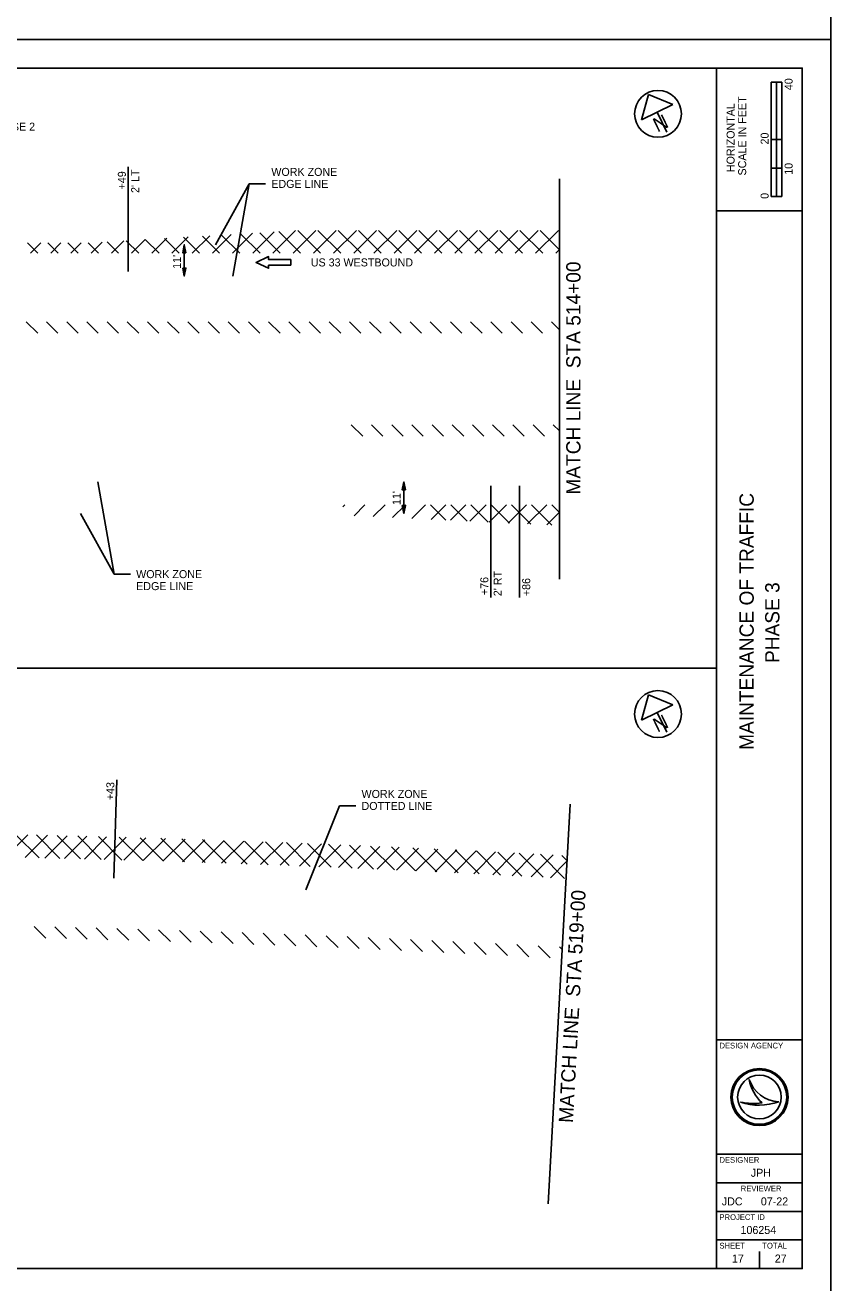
# Model space of a CAD drawing. Extents: x 0 to 5770, y -1320 to 440.
# Drawn here: x 3758.5 to 4040.6, y -435 to 5 of the extents above; entities that cross this region are included whole.
import ezdxf

# ---------------------------------------------------------------- set-up
doc = ezdxf.new("R2010")
doc.units = 0
for name, color, linetype in [('_CIVIL_CONSTRUCTION', 7, 'Continuous'), ('GE_P_Alignment', 7, 'Continuous'), ('GE_P_Alignment_100_Bearings', 7, 'Continuous'), ('GE_P_Alignment_100_Cardinal_Points', 7, 'Continuous'), ('GE_P_Alignment_100_Curve_Data', 7, 'Continuous'), ('GE_P_Alignment_100_Distances', 7, 'Continuous'), ('GE_P_Alignment_100_Stations', 7, 'Continuous'), ('HY_X_Water_Edge', 7, 'Continuous')]:
    doc.layers.add(name, color=color, linetype=linetype)

msp = doc.modelspace()

# ---------------------------------------------------------------- linework, layer by layer
at = {"layer": '_CIVIL_CONSTRUCTION'}
for points in [[(3360.58, 0), (4040.58, 0), (4040.58, 440), (3360.58, 440)], [(3360.58, -440), (4040.58, -440), (4040.58, 0), (3360.58, 0)]]:
    msp.add_lwpolyline(points, close=True, dxfattribs=at)
at = {"layer": 'GE_P_Alignment'}
for p, q in [((4000.58, -430), (4000.58, -10)), ((4000.58, -60), (4030.58, -60)), ((4000.58, -350), (4030.58, -350)), ((4000.58, -390), (4030.58, -390)), ((4000.58, -400), (4030.58, -400)), ((4000.58, -410), (4030.58, -410)), ((4000.58, -420), (4030.58, -420))]:
    msp.add_line(p, q, dxfattribs=at)
msp.add_lwpolyline([(3390.58, -10), (4030.58, -10), (4030.58, -430), (3390.58, -430)], close=True, dxfattribs=at)
at = {"layer": 'GE_P_Alignment_100_Bearings'}
for p, q in [((4019.71, -55), (4019.71, -15)), ((4023.46, -15), (4019.71, -15)), ((4019.71, -35), (4019.71, -15)), ((4019.71, -15), (4021.58, -15)), ((4021.58, -15), (4021.6, -15)), ((4021.6, -15), (4021.6, -35)), ((4023.46, -15), (4023.46, -55)), ((4021.6, -35), (4019.71, -35)), ((4023.45, -35), (4021.58, -35)), ((4021.58, -35), (4021.58, -45)), ((4023.45, -45), (4023.45, -35)), ((4021.58, -45), (4019.71, -45)), ((4019.71, -45), (4019.71, -55)), ((4021.58, -55), (4021.58, -45)), ((4021.58, -45), (4023.45, -45)), ((4023.46, -55), (4019.71, -55)), ((4019.71, -55), (4021.58, -55)), ((4011.93, -363.81), (4011.93, -363.81)), ((4008.92, -371.81), (4008.92, -371.81)), ((4015.58, -370), (4015.58, -370)), ((4022.32, -371.63), (4022.33, -371.63)), ((4008.08, -426.5), (4008.08, -426.5)), ((4015.58, -430), (4015.58, -424))]:
    msp.add_line(p, q, dxfattribs=at)
for radius in [10, 9.54, 9.54, 7.64]:
    msp.add_circle((4015.58, -370), radius, dxfattribs=at)
for centre, radius, start, end in [((4022.9, -360.05), 11.6, 198.9257, 198.9319), ((4027.51, -360.6), 15.91, 191.6379, 191.6421), ((4022.9, -360.05), 11.6, 198.9319, 267.1657), ((4027.51, -360.6), 15.91, 191.6421, 226.0947), ((4015.37, -352.6), 20.26, 251.4576, 290.0832), ((4013.54, -346.91), 25.32, 259.4964, 259.4995), ((4015.37, -352.6), 20.26, 251.4527, 251.4576), ((4013.54, -346.91), 25.32, 259.4995, 276.6672)]:
    msp.add_arc(centre, radius, start, end, dxfattribs=at)
at = {"layer": 'GE_P_Alignment_100_Cardinal_Points'}
for p, q in [((3976.79, -19.28), (3974.23, -28.11)), ((3985.3, -22.75), (3976.79, -19.28)), ((3974.23, -28.11), (3985.3, -22.75)), ((3979.76, -25.43), (3983.13, -32.39)), ((3390.58, -220), (4000.58, -220)), ((3976.79, -229.28), (3974.23, -238.11)), ((3974.23, -238.11), (3985.3, -232.75)), ((3985.3, -232.75), (3976.79, -229.28)), ((3979.76, -235.43), (3983.13, -242.39))]:
    msp.add_line(p, q, dxfattribs=at)
for centre in [(3980.05, -26.01), (3980.05, -236.01)]:
    msp.add_circle(centre, 8.2, dxfattribs=at)
at = {"layer": 'GE_P_Alignment_100_Curve_Data'}
for p, q in [((3794.58, -81.13), (3794.58, -44.58)), ((3836.99, -50.54), (3825.17, -71.8)), ((3836.99, -50.54), (3831.23, -82.8)), ((3842.69, -50.54), (3836.99, -50.54)), ((3945.58, -188.8), (3945.58, -48.8)), ((3814.23, -71.8), (3814.23, -82.8)), ((3789.66, -187.05), (3783.9, -154.8)), ((3891.11, -154.8), (3891.11, -165.8)), ((3921.58, -156.14), (3921.58, -195.2)), ((3931.58, -156.14), (3931.58, -195.2)), ((3789.66, -187.05), (3777.84, -165.8)), ((3795.36, -187.05), (3789.66, -187.05)), ((3789.6, -293.45), (3790.55, -259.02)), ((3868.56, -268.16), (3856.75, -297.5)), ((3874.27, -268.16), (3868.56, -268.16)), ((3941.57, -407.38), (3949.27, -267.59))]:
    msp.add_line(p, q, dxfattribs=at)
msp.add_lwpolyline([(3851.52, -79.01), (3843.72, -79.01), (3843.72, -80.04), (3839.38, -78.01), (3843.72, -75.99), (3843.72, -77.01), (3851.52, -77.01)], close=True, dxfattribs=at)
at = {"layer": 'GE_P_Alignment_100_Distances'}
for points in [[(3814.79, -74.6), (3813.67, -74.6), (3814.23, -71.8)], [(3813.67, -80), (3814.79, -80), (3814.23, -82.8)], [(3891.67, -157.6), (3890.55, -157.6), (3891.11, -154.8)], [(3890.55, -163), (3891.67, -163), (3891.11, -165.8)]]:
    msp.add_lwpolyline(points, close=True, dxfattribs=at)
at = {"layer": 'GE_P_Alignment_100_Stations'}
for p, q in [((3793.91, -70.4), (3798.31, -74.8)), ((3800.56, -70), (3795.76, -74.8)), ((3800.58, -70), (3805.38, -74.8)), ((3808.07, -69.56), (3802.83, -74.8)), ((3807.26, -69.6), (3812.45, -74.8)), ((3815.59, -69.11), (3809.9, -74.8)), ((3813.93, -69.21), (3819.52, -74.8)), ((3823.11, -68.67), (3816.98, -74.8)), ((3820.61, -68.81), (3826.59, -74.8)), ((3830.62, -68.22), (3824.05, -74.8)), ((3827.28, -68.42), (3833.66, -74.8)), ((3838.14, -67.77), (3831.12, -74.8)), ((3833.96, -68.02), (3840.73, -74.8)), ((3845.66, -67.33), (3838.19, -74.8)), ((3840.63, -67.63), (3847.81, -74.8)), ((3853.17, -66.88), (3845.26, -74.8)), ((3847.31, -67.23), (3854.88, -74.8)), ((3860.33, -66.8), (3852.33, -74.8)), ((3853.98, -66.83), (3861.95, -74.8)), ((3867.4, -66.8), (3859.4, -74.8)), ((3861.02, -66.8), (3869.02, -74.8)), ((3874.47, -66.8), (3866.47, -74.8)), ((3868.09, -66.8), (3876.09, -74.8)), ((3881.54, -66.8), (3873.54, -74.8)), ((3875.16, -66.8), (3883.16, -74.8)), ((3888.61, -66.8), (3880.61, -74.8)), ((3882.23, -66.8), (3890.23, -74.8)), ((3895.69, -66.8), (3887.69, -74.8)), ((3889.3, -66.8), (3897.3, -74.8)), ((3902.76, -66.8), (3894.76, -74.8)), ((3896.37, -66.8), (3904.37, -74.8)), ((3909.83, -66.8), (3901.83, -74.8)), ((3903.45, -66.8), (3911.45, -74.8)), ((3916.9, -66.8), (3908.9, -74.8)), ((3910.52, -66.8), (3918.52, -74.8)), ((3923.97, -66.8), (3915.97, -74.8)), ((3917.59, -66.8), (3925.59, -74.8)), ((3931.04, -66.8), (3923.04, -74.8)), ((3924.66, -66.8), (3932.66, -74.8)), ((3938.11, -66.8), (3930.11, -74.8)), ((3931.73, -66.8), (3939.73, -74.8)), ((3945.18, -66.8), (3937.18, -74.8)), ((3938.8, -66.8), (3945.58, -73.58)), ((3759.37, -71.21), (3762.95, -74.8)), ((3763.99, -71.21), (3760.41, -74.8)), ((3766.44, -71.21), (3770.02, -74.8)), ((3771.06, -71.21), (3767.48, -74.8)), ((3773.51, -71.21), (3777.1, -74.8)), ((3778.13, -71.21), (3774.55, -74.8)), ((3780.56, -71.19), (3784.17, -74.8)), ((3785.52, -70.89), (3781.62, -74.8)), ((3787.23, -70.79), (3791.24, -74.8)), ((3793.04, -70.45), (3788.69, -74.8)), ((3945.58, -73.47), (3944.25, -74.8)), ((3758.9, -98.8), (3762.9, -102.8)), ((3765.97, -98.8), (3769.97, -102.8)), ((3773.05, -98.8), (3777.05, -102.8)), ((3780.12, -98.8), (3784.12, -102.8)), ((3787.19, -98.8), (3791.19, -102.8)), ((3794.26, -98.8), (3798.26, -102.8)), ((3801.33, -98.8), (3805.33, -102.8)), ((3808.4, -98.8), (3812.4, -102.8)), ((3815.47, -98.8), (3819.47, -102.8)), ((3822.54, -98.8), (3826.54, -102.8)), ((3829.61, -98.8), (3833.61, -102.8)), ((3836.69, -98.8), (3840.69, -102.8)), ((3843.76, -98.8), (3847.76, -102.8)), ((3850.83, -98.8), (3854.83, -102.8)), ((3857.9, -98.8), (3861.9, -102.8)), ((3864.97, -98.8), (3868.97, -102.8)), ((3872.04, -98.8), (3876.04, -102.8)), ((3879.11, -98.8), (3883.11, -102.8)), ((3886.18, -98.8), (3890.18, -102.8)), ((3893.25, -98.8), (3897.25, -102.8)), ((3900.32, -98.8), (3904.32, -102.8)), ((3907.4, -98.8), (3911.4, -102.8)), ((3914.47, -98.8), (3918.47, -102.8)), ((3921.54, -98.8), (3925.54, -102.8)), ((3928.61, -98.8), (3932.61, -102.8)), ((3935.68, -98.8), (3939.68, -102.8)), ((3942.75, -98.8), (3945.58, -101.63)), ((3872.69, -134.8), (3876.69, -138.8)), ((3879.76, -134.8), (3883.76, -138.8)), ((3886.83, -134.8), (3890.83, -138.8)), ((3893.9, -134.8), (3897.9, -138.8)), ((3900.97, -134.8), (3904.97, -138.8)), ((3908.04, -134.8), (3912.04, -138.8)), ((3915.11, -134.8), (3919.11, -138.8)), ((3922.18, -134.8), (3926.18, -138.8)), ((3929.25, -134.8), (3933.25, -138.8)), ((3936.32, -134.8), (3940.32, -138.8)), ((3943.4, -134.8), (3945.58, -136.98)), ((3870.4, -162.8), (3869.69, -163.51)), ((3877.47, -162.8), (3873.64, -166.63)), ((3884.54, -162.8), (3880.39, -166.95)), ((3891.61, -162.8), (3887.14, -167.27)), ((3898.68, -162.8), (3893.89, -167.59)), ((3900.45, -162.8), (3905.8, -168.15)), ((3905.75, -162.8), (3900.64, -167.91)), ((3912.82, -162.8), (3907.39, -168.23)), ((3907.52, -162.8), (3913.23, -168.5)), ((3919.89, -162.8), (3914.15, -168.55)), ((3914.59, -162.8), (3920.65, -168.85)), ((3926.97, -162.8), (3920.9, -168.87)), ((3921.66, -162.8), (3928.07, -169.21)), ((3934.04, -162.8), (3927.65, -169.19)), ((3928.73, -162.8), (3935.5, -169.56)), ((3941.11, -162.8), (3934.4, -169.51)), ((3935.81, -162.8), (3942.92, -169.91)), ((3942.88, -162.8), (3945.58, -165.5)), ((3945.58, -165.4), (3941.15, -169.83)), ((3759.44, -278.25), (3751.61, -286.08)), ((3755.19, -278.15), (3763.38, -286.34)), ((3766.35, -278.41), (3758.53, -286.23)), ((3762.43, -278.32), (3770.62, -286.51)), ((3773.25, -278.57), (3765.44, -286.39)), ((3769.67, -278.49), (3777.87, -286.69)), ((3780.15, -278.75), (3772.34, -286.55)), ((3776.92, -278.67), (3785.14, -286.88)), ((3787.04, -278.93), (3779.24, -286.73)), ((3784.18, -278.85), (3792.41, -287.08)), ((3793.92, -279.12), (3786.13, -286.91)), ((3791.45, -279.05), (3799.69, -287.29)), ((3800.79, -279.32), (3793.01, -287.1)), ((3798.73, -279.26), (3806.98, -287.51)), ((3807.65, -279.53), (3799.88, -287.3)), ((3806.02, -279.48), (3814.28, -287.74)), ((3814.51, -279.74), (3806.75, -287.5)), ((3813.31, -279.71), (3821.59, -287.98)), ((3821.36, -279.97), (3813.61, -287.72)), ((3828.2, -280.2), (3820.45, -287.94)), ((3820.62, -279.94), (3828.91, -288.23)), ((3835.03, -280.44), (3827.3, -288.17)), ((3827.94, -280.19), (3836.23, -288.48)), ((3841.86, -280.68), (3834.13, -288.41)), ((3835.26, -280.44), (3843.57, -288.75)), ((3848.67, -280.94), (3840.95, -288.65)), ((3842.6, -280.71), (3850.92, -289.03)), ((3855.48, -281.2), (3847.77, -288.91)), ((3849.95, -280.98), (3858.28, -289.31)), ((3862.28, -281.47), (3854.58, -289.17)), ((3857.3, -281.27), (3865.64, -289.61)), ((3864.67, -281.56), (3873.02, -289.92)), ((3869.08, -281.74), (3861.38, -289.44)), ((3875.86, -282.03), (3868.18, -289.71)), ((3872.04, -281.87), (3880.41, -290.23)), ((3882.64, -282.32), (3874.97, -290)), ((3879.43, -282.18), (3887.81, -290.56)), ((3889.41, -282.62), (3881.75, -290.29)), ((3886.82, -282.51), (3895.21, -290.89)), ((3896.18, -282.93), (3888.52, -290.59)), ((3894.23, -282.84), (3902.63, -291.24)), ((3902.93, -283.25), (3895.28, -290.9)), ((3901.65, -283.18), (3910.06, -291.6)), ((3909.68, -283.57), (3902.04, -291.21)), ((3916.42, -283.9), (3908.79, -291.53)), ((3909.07, -283.54), (3917.49, -291.96)), ((3923.15, -284.24), (3915.53, -291.86)), ((3916.51, -283.9), (3924.94, -292.34)), ((3929.88, -284.58), (3922.26, -292.2)), ((3923.95, -284.28), (3932.4, -292.72)), ((3936.6, -284.93), (3928.99, -292.55)), ((3931.41, -284.66), (3939.87, -293.12)), ((3943.31, -285.3), (3935.71, -292.9)), ((3938.87, -285.06), (3947.34, -293.53)), ((3946.35, -285.46), (3948.19, -287.3)), ((3948.18, -287.5), (3942.42, -293.26)), ((3761.63, -310.31), (3765.72, -314.4)), ((3768.87, -310.48), (3772.97, -314.58)), ((3776.12, -310.66), (3780.23, -314.76)), ((3783.38, -310.84), (3787.49, -314.96)), ((3790.65, -311.04), (3794.77, -315.16)), ((3797.93, -311.25), (3802.05, -315.38)), ((3805.22, -311.47), (3809.35, -315.6)), ((3812.52, -311.7), (3816.65, -315.83)), ((3819.82, -311.93), (3823.96, -316.07)), ((3827.14, -312.18), (3831.29, -316.33)), ((3834.47, -312.44), (3838.62, -316.59)), ((3841.81, -312.7), (3845.96, -316.86)), ((3849.15, -312.98), (3853.32, -317.14)), ((3856.51, -313.26), (3860.68, -317.43)), ((3863.87, -313.56), (3868.05, -317.73)), ((3871.25, -313.86), (3875.43, -318.04)), ((3878.64, -314.18), (3882.82, -318.36)), ((3886.03, -314.5), (3890.23, -318.7)), ((3893.44, -314.84), (3897.64, -319.04)), ((3900.85, -315.18), (3905.06, -319.39)), ((3908.28, -315.54), (3912.49, -319.75)), ((3915.72, -315.9), (3919.93, -320.12)), ((3923.16, -316.28), (3927.39, -320.5)), ((3930.62, -316.66), (3934.85, -320.89)), ((3938.09, -317.06), (3942.32, -321.29)), ((3945.56, -317.47), (3946.47, -318.37))]:
    msp.add_line(p, q, dxfattribs=at)
at = {"layer": 'HY_X_Water_Edge'}
for centre in [(3980.05, -26.01), (3980.05, -236.01)]:
    msp.add_circle(centre, 8.2, dxfattribs=at)

# ---------------------------------------------------------------- texts
at = {"layer": 'GE_P_Alignment_100_Bearings'}
for s, height, rotation, p in [('40', 2.8, 90, (4027.19, -17.75)), ('SCALE IN FEET', 2.8, 90, (4010.93, -47.59)), ('HORIZONTAL', 2.8, 90, (4006.88, -46.42)), ('20', 2.8, 90, (4018.79, -36.75)), ('10', 2.8, 90, (4027.19, -47.35)), ('0', 2.8, 90, (4018.79, -55.77)), ('MATCH LINE  STA 514+00', 5, 90, (3952.93, -159.24)), ('MAINTENANCE OF TRAFFIC', 5, 90, (4013.58, -248.55)), ('PHASE 3', 5, 90, (4022.58, -218.15)), ('MATCH LINE  STA 519+00', 5, 86.8439, (3950.28, -379.14))]:
    msp.add_text(s, height=height, rotation=rotation, dxfattribs=at).set_placement(p)
for s, height, p in [('DESIGN AGENCY', 2, (4001.58, -353)), ('DESIGNER', 2, (4001.58, -393)), ('JPH', 2.8, (4012.55, -397.9)), ('REVIEWER', 2, (4009.02, -403)), ('JDC', 2.8, (4002.4, -407.9)), ('07-22', 2.8, (4016.06, -407.9)), ('PROJECT ID', 2, (4001.58, -413)), ('106254', 2.8, (4008.94, -417.9)), ('SHEET', 2, (4001.58, -423)), ('TOTAL', 2, (4016.58, -423)), ('17', 2.8, (4005.95, -427.9)), ('27', 2.8, (4020.95, -427.9))]:
    msp.add_text(s, height=height, dxfattribs=at).set_placement(p)
at = {"layer": 'GE_P_Alignment_100_Cardinal_Points'}
for p in [(3979.86, -32.57), (3979.86, -242.57)]:
    msp.add_text('N', height=5, rotation=25.8319, dxfattribs=at).set_placement(p)
at = {"layer": 'GE_P_Alignment_100_Curve_Data'}
for s, p in [('  CLASS A, AS PER PLAN BUILT DURING PHASE 2', (3673.14, -31.91)), ('WORK ZONE', (3844.69, -47.74)), ('EDGE LINE', (3844.69, -51.94)), ('US 33 WESTBOUND', (3858.52, -79.41)), ('WORK ZONE', (3797.37, -188.45)), ('EDGE LINE', (3797.37, -192.65)), ('WORK ZONE', (3876.27, -265.36)), ('DOTTED LINE', (3876.27, -269.56))]:
    msp.add_text(s, height=2.8, dxfattribs=at).set_placement(p)
for s, rotation, p in [('+49', 90, (3793.76, -52.47)), ("2' LT", 90, (3798.43, -53.71)), ("11'", 90, (3813.04, -80.25)), ("11'", 90, (3889.92, -162.88)), ('+76', 90, (3920.66, -194.4)), ("2' RT", 90, (3925.33, -194.78)), ('+86', 90, (3935.33, -194.77)), ('+43', 88.4139, (3789.58, -266.19))]:
    msp.add_text(s, height=2.8, rotation=rotation, dxfattribs=at).set_placement(p)

doc.saveas('drawing.dxf')
